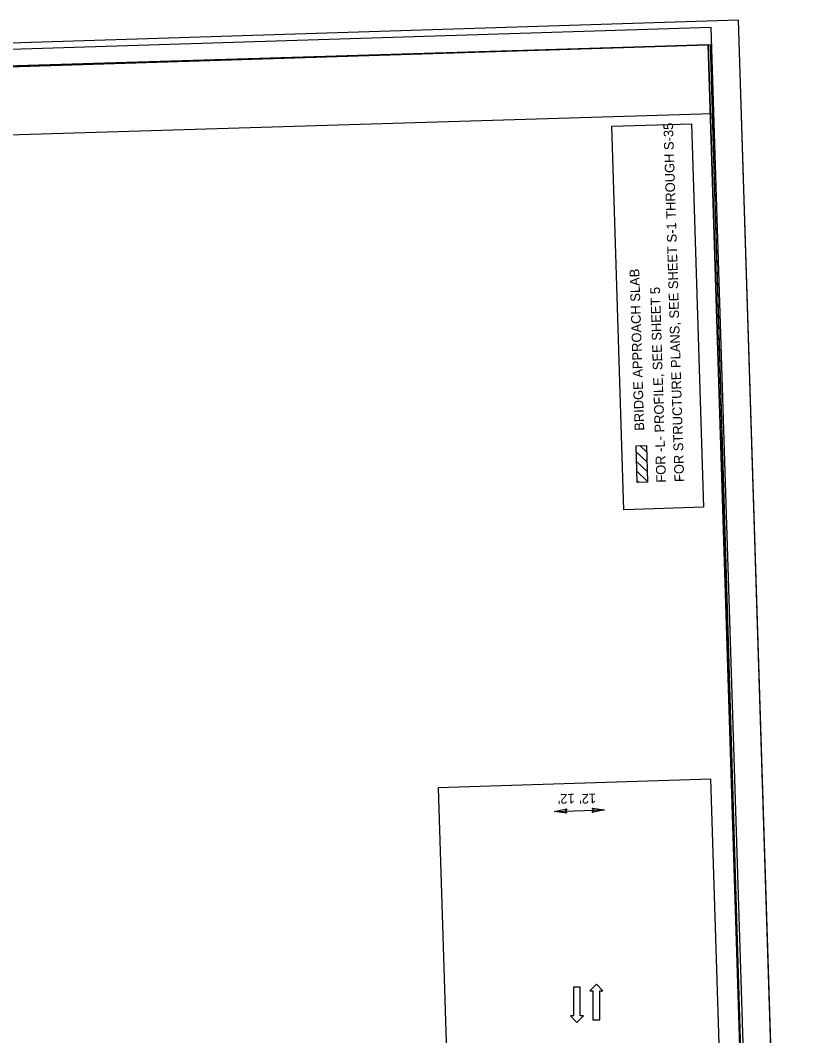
# Model space of a CAD drawing. Extents: x 2326025 to 2327173, y 123144 to 125024.
# Drawn here: x 2326599 to 2327173, y 124287 to 125024 of the extents above; entities that cross this region are included whole.
import ezdxf

# ---------------------------------------------------------------- set-up
doc = ezdxf.new("R2010")
doc.units = 0
for name, color, linetype in [('Exist Feeder Circuit Designator CELL', 7, 'Continuous'), ('Prop Approach Slab', 7, 'Continuous'), ('Prop Dimension Text', 7, 'Continuous'), ('Prop DSN Text', 7, 'Continuous'), ('Prop Lane Arrow CELL', 7, 'Continuous'), ('Prop Terminator CELL', 7, 'Continuous'), ('Sheet Clip Boundary CELL', 7, 'Continuous'), ('Sheet Cutting Line CELL', 7, 'Continuous'), ('Sheet Layout Plan Border', 7, 'Continuous'), ('Sheet Plan CELL', 7, 'Continuous'), ('Sheet Plan Layout CELL', 7, 'Continuous'), ('Sheet Plot Border Inside CELL', 7, 'Continuous'), ('Sheet Plot Border Outside CELL', 7, 'Continuous')]:
    doc.layers.add(name, color=color, linetype=linetype)

# ---------------------------------------------------------------- blocks, each defined once
blk = doc.blocks.new('Lane Arrow Through')
at = {"layer": 'Prop Lane Arrow CELL'}
for p, q in [((-17.15, 1.6), (-3.15, 1.6)), ((-17.15, -1.7), (-17.15, 1.6)), ((-3.15, 1.6), (-3.15, 3.1)), ((-3.15, 3.1), (0, 0)), ((0, 0), (-3.15, -3.2)), ((-3.15, -1.7), (-17.15, -1.7)), ((-3.15, -3.2), (-3.15, -1.7))]:
    blk.add_line(p, q, dxfattribs=at)

msp = doc.modelspace()

# ---------------------------------------------------------------- linework, layer by layer
at = {"layer": 'Prop Approach Slab'}
for p, q in [((2327053.54, 124703.47), (2327045.76, 124710.78)), ((2327053.32, 124710.54), (2327048.3, 124715.25)), ((2327053.76, 124696.4), (2327045.98, 124703.71)), ((2327053.99, 124689.33), (2327046.2, 124696.64)), ((2327047.53, 124688.54), (2327046.43, 124689.57))]:
    msp.add_line(p, q, dxfattribs=at)
msp.add_lwpolyline([(2327046.46, 124688.5), (2327045.62, 124715.16), (2327053.17, 124715.4), (2327054.01, 124688.74)], close=True, dxfattribs=at)
at = {"layer": 'Prop DSN Text'}
msp.add_line((2326986.33, 124449.96), (2327022.81, 124451.16), dxfattribs=at)
for points in [[(2327036.71, 124668.74), (2327027.95, 124946.77), (2327085.73, 124948.59), (2327094.49, 124670.56)], [(2327123.69, 123713.23), (2327099.74, 124473.33), (2326902.04, 124467.1), (2326925.99, 123707)]]:
    msp.add_lwpolyline(points, close=True, dxfattribs=at)
at = {"layer": 'Prop Terminator CELL'}
for points in [[(2326995.37, 124448.71), (2326986.33, 124449.96), (2326995.32, 124451.86), (2326994.22, 124450.22)], [(2327013.76, 124452.42), (2327022.81, 124451.16), (2327013.81, 124449.27), (2327014.91, 124450.9)]]:
    msp.add_lwpolyline(points, close=True, dxfattribs=at)
at = {"layer": 'Sheet Clip Boundary CELL'}
msp.add_lwpolyline([(2327143.22, 123556.44), (2327101.01, 124955.82), (2326262.87, 124930.53), (2326268.58, 124741.36), (2326057.19, 124734.98), (2326093.7, 123524.78)], close=True, dxfattribs=at)
at = {"layer": 'Sheet Cutting Line CELL'}
msp.add_line((2327172.95, 123340.96), (2327119.93, 125023.63), dxfattribs=at)
at = {"layer": 'Sheet Layout Plan Border'}
msp.add_lwpolyline([(2327143.22, 123556.44), (2327101.01, 124955.82), (2326262.87, 124930.53), (2326268.58, 124741.36), (2326057.19, 124734.98), (2326093.7, 123524.78)], close=True, dxfattribs=at)
at = {"layer": 'Sheet Plan CELL'}
for points in [[(2326048.48, 124972.88), (2326095.72, 123473.59), (2327145.2, 123506.66), (2327097.96, 125005.93)], [(2327145.2, 123506.66), (2326095.75, 123473.57), (2326054.77, 124772.91), (2326204.76, 124777.65), (2326198.47, 124977.58), (2327097.96, 125005.93)]]:
    msp.add_lwpolyline(points, close=True, dxfattribs=at)
at = {"layer": 'Sheet Plan Layout CELL'}
msp.add_lwpolyline([(2326095.24, 123474.78), (2327144.73, 123506.47), (2327099.5, 125005.78), (2326261.37, 124980.5), (2326268.58, 124741.36), (2326057.19, 124734.98)], close=True, dxfattribs=at)
at = {"layer": 'Sheet Plot Border Inside CELL'}
msp.add_lwpolyline([(2327152.55, 123353.33), (2327100.07, 125018.49), (2326045.6, 124985.27), (2326098.07, 123320.1)], close=True, dxfattribs=at)
at = {"layer": 'Sheet Plot Border Outside CELL'}
msp.add_lwpolyline([(2327172.95, 123340.96), (2327119.93, 125023.63), (2326025.47, 124989.14), (2326078.49, 123306.48)], close=True, dxfattribs=at)

# ---------------------------------------------------------------- block references
at = {"layer": 'Exist Feeder Circuit Designator CELL', "xscale": 1.5000000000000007, "yscale": -1.4999999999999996}
for p, rotation in [((2327002.63, 124296.97), -90), ((2327016.89, 124324.74), 90.00000000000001)]:
    msp.add_blockref('Lane Arrow Through', p, dxfattribs=dict(at, rotation=rotation))

# ---------------------------------------------------------------- texts
at = {"layer": 'Prop Dimension Text'}
for s, p in [('FOR STRUCTURE PLANS, SEE SHEET S-1 THROUGH S-35', (2327080.54, 124688.98)), ('BRIDGE APPROACH SLAB', (2327051.57, 124726.13)), ('FOR -L- PROFILE, SEE SHEET 5', (2327067.35, 124688.48))]:
    msp.add_text(s, height=7, rotation=91.79128, dxfattribs=at).set_placement(p)
at = {"layer": 'Prop DSN Text'}
for p in [(2327001.01, 124462.86), (2327016.51, 124462.97)]:
    msp.add_text("12'", height=7, rotation=181.88146, dxfattribs=at).set_placement(p)

doc.saveas('drawing.dxf')
